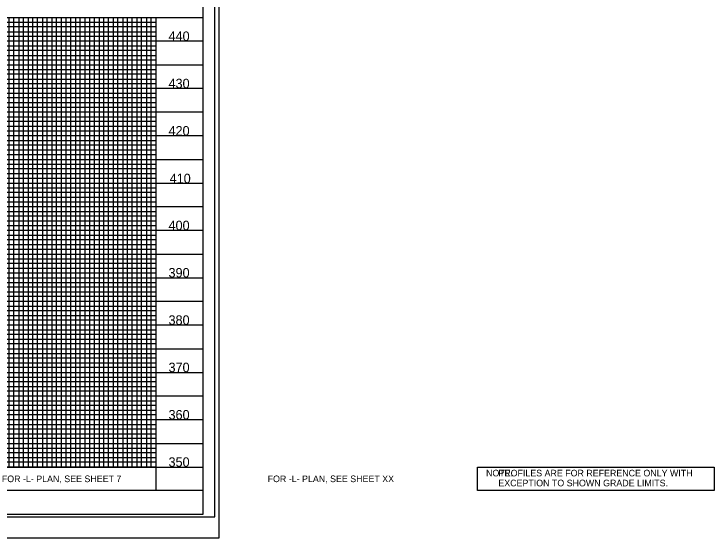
# Model space of a CAD drawing. Extents: x 1632687 to 1634895, y 1174336 to 1175436.
# Drawn here: x 1634154 to 1634895, y 1174336 to 1174889 of the extents above; entities that cross this region are included whole.
import ezdxf

# ---------------------------------------------------------------- set-up
doc = ezdxf.new("R2010")
doc.units = 0
for name, color, linetype in [('Exist Vertical Profile Vertical Axis Label', 7, 'Continuous'), ('Prop Dimension Text', 7, 'Continuous'), ('Sheet Data Field CELL', 7, 'Continuous'), ('Sheet Layout Profile Border Port 2', 7, 'Continuous'), ('Sheet Plot Border Inside CELL', 7, 'Continuous'), ('Sheet Plot Border Outside CELL', 7, 'Continuous'), ('Sheet Profile CELL', 7, 'Continuous'), ('Sheet Profile Grid Major CELL', 7, 'Continuous'), ('Sheet Profile Grid Middle CELL', 7, 'Continuous'), ('Sheet Profile Grid Minor CELL', 7, 'Continuous')]:
    doc.layers.add(name, color=color, linetype=linetype)

msp = doc.modelspace()

# ---------------------------------------------------------------- linework, layer by layer
at = {"layer": 'Sheet Data Field CELL'}
for points in [[(1634304.31, 1174385.79), (1634104.31, 1174385.79), (1634104.31, 1174410.79), (1634304.31, 1174410.79)], [(1634894.74, 1174385.79), (1634644.74, 1174385.79), (1634644.74, 1174410.79), (1634894.74, 1174410.79)]]:
    msp.add_lwpolyline(points, close=True, dxfattribs=at)
at = {"layer": 'Sheet Layout Profile Border Port 2'}
msp.add_lwpolyline([(1632904.31, 1174885.79), (1634304.31, 1174885.79), (1634304.31, 1174410.79), (1634104.31, 1174410.79), (1634104.31, 1174385.79), (1633684.31, 1174385.79), (1633684.31, 1174405.79), (1633524.31, 1174405.79), (1633524.31, 1174385.79), (1632904.31, 1174385.79)], close=True, dxfattribs=at)
at = {"layer": 'Sheet Plot Border Inside CELL'}
msp.add_lwpolyline([(1632700.31, 1174358.24), (1634366.81, 1174358.24), (1634366.81, 1175413.34), (1632700.31, 1175413.34)], close=True, dxfattribs=at)
at = {"layer": 'Sheet Plot Border Outside CELL'}
msp.add_lwpolyline([(1632687.31, 1174335.79), (1634371.31, 1174335.79), (1634371.31, 1175435.79), (1632687.31, 1175435.79)], close=True, dxfattribs=at)
at = {"layer": 'Sheet Profile CELL'}
for p, q in [((1632854.31, 1174885.79), (1634354.31, 1174885.79)), ((1634354.31, 1174385.79), (1632854.31, 1174385.79)), ((1632854.31, 1174360.79), (1634354.31, 1174360.79))]:
    msp.add_line(p, q, dxfattribs=at)
msp.add_lwpolyline([(1634354.31, 1175410.79), (1632854.31, 1175410.79), (1632854.31, 1174360.79), (1634354.31, 1174360.79)], close=True, dxfattribs=at)
at = {"layer": 'Sheet Profile Grid Major CELL'}
for p, q in [((1634154.31, 1174885.79), (1634204.31, 1174885.79)), ((1634254.31, 1174885.79), (1634304.31, 1174885.79)), ((1634254.31, 1174885.79), (1634304.31, 1174885.79)), ((1634254.31, 1174410.79), (1634254.31, 1174885.79)), ((1634304.31, 1174885.79), (1634304.31, 1174385.79))]:
    msp.add_line(p, q, dxfattribs=at)
for points in [[(1634154.31, 1174410.79), (1634154.31, 1174885.79), (1634204.31, 1174885.79), (1634204.31, 1174410.79)], [(1634354.31, 1174860.79), (1632854.31, 1174860.79)], [(1634354.31, 1174810.79), (1632854.31, 1174810.79)], [(1634354.31, 1174760.79), (1632854.31, 1174760.79), (1632854.31, 1174710.79), (1634354.31, 1174710.79)], [(1634354.31, 1174660.79), (1632854.31, 1174660.79), (1632854.31, 1174610.79), (1634354.31, 1174610.79)], [(1634354.31, 1174560.79), (1632854.31, 1174560.79), (1632854.31, 1174510.79), (1634354.31, 1174510.79)], [(1634354.31, 1174460.79), (1632854.31, 1174460.79), (1632854.31, 1174460.79), (1632854.31, 1174410.79), (1634354.31, 1174410.79)], [(1634354.31, 1174385.79), (1632854.31, 1174385.79)]]:
    msp.add_lwpolyline(points, dxfattribs=at)
at = {"layer": 'Sheet Profile Grid Middle CELL'}
for points in [[(1634179.31, 1174410.79), (1634179.31, 1174885.79), (1634229.31, 1174885.79), (1634229.31, 1174410.79)], [(1634279.31, 1174410.79), (1634279.31, 1174885.79)], [(1632854.31, 1174835.79), (1634354.31, 1174835.79)], [(1634354.31, 1174785.79), (1632854.31, 1174785.79), (1632854.31, 1174735.79), (1634354.31, 1174735.79)], [(1634354.31, 1174685.79), (1632854.31, 1174685.79), (1632854.31, 1174635.79), (1634354.31, 1174635.79)], [(1634354.31, 1174585.79), (1632854.31, 1174585.79), (1632854.31, 1174535.79), (1634354.31, 1174535.79)], [(1634354.31, 1174485.79), (1632854.31, 1174485.79), (1632854.31, 1174435.79), (1634354.31, 1174435.79)], [(1634354.31, 1174385.79), (1632854.31, 1174385.79)]]:
    msp.add_lwpolyline(points, dxfattribs=at)
at = {"layer": 'Sheet Profile Grid Minor CELL'}
for p, q in [((1632904.31, 1174880.79), (1634304.31, 1174880.79)), ((1634304.31, 1174875.79), (1632904.31, 1174875.79)), ((1632904.31, 1174870.79), (1634304.31, 1174870.79)), ((1634304.31, 1174865.79), (1632904.31, 1174865.79)), ((1632904.31, 1174855.79), (1634304.31, 1174855.79)), ((1634304.31, 1174850.79), (1632904.31, 1174850.79)), ((1632904.31, 1174845.79), (1634304.31, 1174845.79)), ((1634304.31, 1174840.79), (1632904.31, 1174840.79)), ((1632904.31, 1174830.79), (1634304.31, 1174830.79)), ((1634304.31, 1174825.79), (1632904.31, 1174825.79)), ((1632904.31, 1174820.79), (1634304.31, 1174820.79)), ((1634304.31, 1174815.79), (1632904.31, 1174815.79)), ((1632904.31, 1174805.79), (1634304.31, 1174805.79)), ((1634304.31, 1174800.79), (1632904.31, 1174800.79)), ((1632904.31, 1174795.79), (1634304.31, 1174795.79)), ((1634304.31, 1174790.79), (1632904.31, 1174790.79)), ((1632904.31, 1174780.79), (1634304.31, 1174780.79)), ((1634304.31, 1174775.79), (1632904.31, 1174775.79)), ((1632904.31, 1174770.79), (1634304.31, 1174770.79)), ((1634304.31, 1174765.79), (1632904.31, 1174765.79)), ((1632904.31, 1174755.79), (1634304.31, 1174755.79)), ((1634304.31, 1174750.79), (1632904.31, 1174750.79)), ((1632904.31, 1174745.79), (1634304.31, 1174745.79)), ((1634304.31, 1174740.79), (1632904.31, 1174740.79)), ((1632904.31, 1174730.79), (1634304.31, 1174730.79)), ((1634304.31, 1174725.79), (1632904.31, 1174725.79)), ((1632904.31, 1174720.79), (1634304.31, 1174720.79)), ((1634304.31, 1174715.79), (1632904.31, 1174715.79)), ((1632904.31, 1174705.79), (1634304.31, 1174705.79)), ((1634304.31, 1174700.79), (1632904.31, 1174700.79)), ((1632904.31, 1174695.79), (1634304.31, 1174695.79)), ((1634304.31, 1174690.79), (1632904.31, 1174690.94)), ((1632904.31, 1174680.79), (1634304.31, 1174680.79)), ((1634304.31, 1174675.79), (1632904.31, 1174675.79)), ((1632904.31, 1174670.79), (1634304.31, 1174670.79)), ((1634304.31, 1174665.79), (1632904.31, 1174665.79)), ((1632904.31, 1174655.79), (1634304.31, 1174655.79)), ((1634304.31, 1174650.79), (1632904.31, 1174650.79)), ((1632904.31, 1174645.79), (1634304.31, 1174645.79)), ((1634304.31, 1174640.79), (1632904.31, 1174640.79)), ((1632904.31, 1174630.79), (1634304.31, 1174630.79)), ((1634304.31, 1174625.79), (1632904.31, 1174625.79)), ((1632904.31, 1174620.79), (1634304.31, 1174620.79)), ((1634304.31, 1174615.79), (1632904.31, 1174615.79)), ((1632904.31, 1174605.79), (1634304.31, 1174605.79)), ((1634304.31, 1174600.79), (1632904.31, 1174600.79)), ((1632904.31, 1174595.79), (1634304.31, 1174595.79)), ((1634304.31, 1174590.79), (1632904.31, 1174590.79)), ((1632904.31, 1174580.79), (1634304.31, 1174580.79)), ((1634304.31, 1174575.79), (1632904.31, 1174575.79)), ((1632904.31, 1174570.79), (1634304.31, 1174570.79)), ((1634304.31, 1174565.79), (1632904.31, 1174565.79)), ((1632904.31, 1174555.79), (1634304.31, 1174555.79)), ((1634304.31, 1174550.79), (1632904.31, 1174550.79)), ((1632904.31, 1174545.79), (1634304.31, 1174545.79)), ((1634304.31, 1174540.79), (1632904.31, 1174540.79)), ((1632904.31, 1174530.79), (1634304.31, 1174530.79)), ((1634304.31, 1174525.79), (1632904.31, 1174525.79)), ((1632904.31, 1174520.79), (1634304.31, 1174520.79)), ((1634304.31, 1174515.79), (1632904.31, 1174515.79)), ((1632904.31, 1174505.79), (1634304.31, 1174505.79)), ((1634304.31, 1174500.79), (1632904.31, 1174500.79)), ((1632904.31, 1174495.79), (1634304.31, 1174495.79)), ((1634304.31, 1174490.79), (1632904.31, 1174490.79)), ((1632904.31, 1174480.79), (1634304.31, 1174480.79)), ((1634304.31, 1174475.79), (1632904.31, 1174475.79)), ((1632904.31, 1174470.79), (1634304.31, 1174470.79)), ((1634304.31, 1174465.79), (1632904.31, 1174465.79)), ((1632904.31, 1174455.79), (1634304.31, 1174455.79)), ((1634304.31, 1174450.79), (1632904.31, 1174450.79)), ((1632904.31, 1174445.79), (1634304.31, 1174445.79)), ((1634304.31, 1174440.79), (1632904.31, 1174440.79)), ((1632904.31, 1174430.79), (1634304.31, 1174430.79)), ((1634304.31, 1174425.79), (1632904.31, 1174425.79)), ((1632904.31, 1174420.79), (1634304.31, 1174420.79)), ((1634304.31, 1174415.79), (1632904.31, 1174415.79))]:
    msp.add_line(p, q, dxfattribs=at)
for points in [[(1634149.31, 1174410.79), (1634149.31, 1174885.79), (1634159.31, 1174885.79), (1634159.31, 1174410.79)], [(1634164.31, 1174410.79), (1634164.31, 1174885.79), (1634169.31, 1174885.79), (1634169.31, 1174410.79)], [(1634174.31, 1174410.79), (1634174.31, 1174885.79), (1634184.31, 1174885.79), (1634184.31, 1174410.79)], [(1634189.31, 1174410.79), (1634189.31, 1174885.79), (1634194.31, 1174885.79), (1634194.31, 1174410.79)], [(1634199.31, 1174410.79), (1634199.31, 1174885.79), (1634209.31, 1174885.79), (1634209.31, 1174410.79)], [(1634214.31, 1174410.79), (1634214.31, 1174885.79), (1634219.31, 1174885.79), (1634219.31, 1174410.79)], [(1634224.31, 1174410.79), (1634224.31, 1174885.79), (1634234.31, 1174885.79), (1634234.31, 1174410.79)], [(1634239.31, 1174410.79), (1634239.31, 1174885.79), (1634244.31, 1174885.79), (1634244.31, 1174410.79)], [(1634249.31, 1174410.79), (1634249.31, 1174885.79), (1634259.31, 1174885.79), (1634259.31, 1174410.79)], [(1634264.31, 1174410.79), (1634264.31, 1174885.79), (1634269.31, 1174885.79), (1634269.31, 1174410.79)], [(1634274.31, 1174410.79), (1634274.31, 1174885.79), (1634284.31, 1174885.79), (1634284.31, 1174410.79)], [(1634289.31, 1174410.79), (1634289.31, 1174885.79), (1634294.31, 1174885.79), (1634294.31, 1174410.79)], [(1634299.31, 1174410.79), (1634299.31, 1174885.79), (1634304.31, 1174885.79)]]:
    msp.add_lwpolyline(points, dxfattribs=at)

# ---------------------------------------------------------------- texts
at = {"layer": 'Exist Vertical Profile Vertical Axis Label'}
for s, p in [('440', (1634317.75, 1174861.04)), ('430', (1634317.75, 1174811.04)), ('420', (1634317.75, 1174761.04)), ('410', (1634318.94, 1174710.69)), ('400', (1634317.75, 1174661.04)), ('390', (1634317.75, 1174611.04)), ('380', (1634317.75, 1174561.04)), ('370', (1634317.75, 1174511.04)), ('360', (1634317.75, 1174461.04)), ('350', (1634317.75, 1174411.04))]:
    msp.add_text(s, height=10, dxfattribs=at).set_placement(p)
at = {"layer": 'Prop Dimension Text'}
msp.add_text('FOR -L- PLAN, SEE SHEET XX', height=7, rotation=360, dxfattribs=at).set_placement((1634422.6, 1174394.79))
at = {"layer": 'Sheet Data Field CELL'}
for s, p in [('NOTE: ', (1634653.64, 1174400.86)), ('     PROFILES ARE FOR REFERENCE ONLY WITH', (1634653.64, 1174400.86)), ('     EXCEPTION TO SHOWN GRADE LIMITS.', (1634653.64, 1174390.36))]:
    msp.add_text(s, height=7, dxfattribs=at).set_placement(p)
msp.add_text('FOR -L- PLAN, SEE SHEET 7', height=7, rotation=360, dxfattribs=at).set_placement((1634141.46, 1174394.79))

doc.saveas('drawing.dxf')
